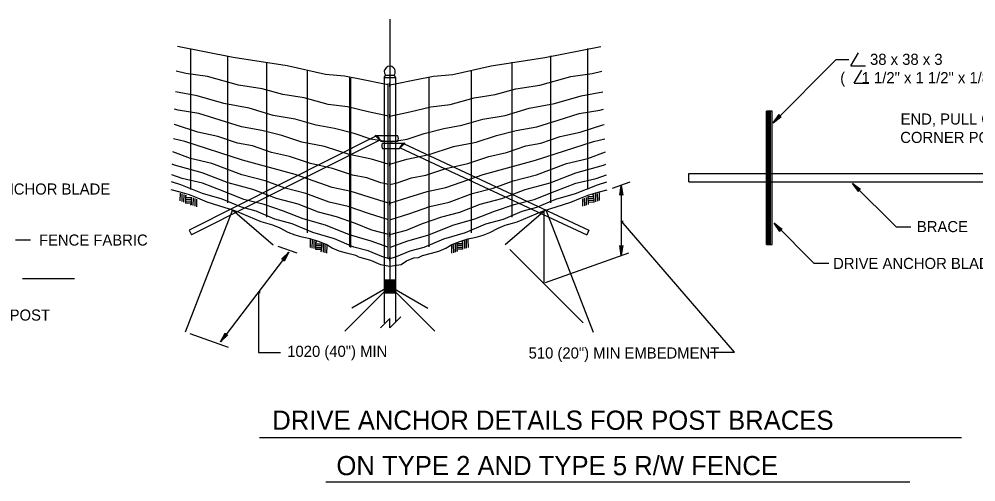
# Model space of a CAD drawing. Extents: x 13 to 918, y -903 to 879.
# Drawn here: x 370 to 639.6, y -696.9 to -566.6 of the extents above; entities that cross this region are included whole.
import ezdxf

# ---------------------------------------------------------------- set-up
doc = ezdxf.new("R2010")
doc.units = 0
for name, color, linetype in [('1', 7, 'Continuous'), ('2', 7, 'Continuous'), ('3', 7, 'Continuous')]:
    doc.layers.add(name, color=color, linetype=linetype)

msp = doc.modelspace()

# ---------------------------------------------------------------- linework, layer by layer
at = {"layer": '1'}
for p, q in [((415.3665, -615.62575), (415.33325, -617.80925)), ((415.879, -615.81125), (415.8415, -617.9945)), ((416.38525, -615.99675), (416.352, -618.178)), ((416.8935, -616.182), (416.86025, -618.36325)), ((416.86025, -617.305), (418.4915, -617.328)), ((416.8685, -616.7925), (418.49975, -616.8195)), ((416.877, -616.282), (417.181, -616.28625)), ((418.502, -616.7675), (418.4685, -618.94875)), ((419.01025, -616.953), (418.977, -619.13425)), ((419.5185, -617.13625), (419.48525, -619.3195)), ((420.029, -617.32175), (419.99575, -619.4655)), ((528.7645, -617.1905), (528.79775, -619.33425)), ((529.27475, -617.005), (529.30825, -619.18825)), ((529.78325, -616.82175), (529.8165, -619.003)), ((530.2915, -616.63625), (530.32475, -618.8175)), ((531.92475, -616.66125), (530.2935, -616.68825)), ((531.93325, -617.17375), (530.302, -617.19675)), ((531.9165, -616.15075), (531.61225, -616.155)), ((531.89975, -616.05075), (531.93325, -618.232)), ((532.40825, -615.8655), (532.4415, -618.04675)), ((532.9145, -615.68), (532.952, -617.86325)), ((533.427, -615.4945), (533.46025, -617.678)), ((416.84575, -618.328), (418.477, -618.355)), ((416.852, -617.8155), (418.48525, -617.8425)), ((418.231, -618.86325), (418.4685, -618.8655)), ((531.9415, -617.68425), (530.30825, -617.71125)), ((531.94775, -618.19675), (530.3165, -618.22375)), ((530.56225, -618.732), (530.32475, -618.73425)), ((452.0435, -628.703), (452.01025, -630.88625)), ((452.556, -628.88825), (452.5185, -631.07175)), ((453.06225, -629.07375), (453.029, -631.255)), ((453.57075, -629.25925), (453.53725, -631.4405)), ((453.53725, -630.382), (455.1685, -630.405)), ((453.54575, -629.8695), (455.177, -629.89675)), ((453.554, -629.35925), (453.85825, -629.36325)), ((455.179, -629.8445), (455.14575, -632.02575)), ((455.68725, -630.03), (455.654, -632.21125)), ((456.19575, -630.21325), (456.16225, -632.39675)), ((456.706, -630.39875), (456.67275, -632.5425)), ((491.827, -630.39875), (491.86025, -632.5425)), ((492.33725, -630.21325), (492.37075, -632.39675)), ((492.84575, -630.03), (492.879, -632.21125)), ((493.354, -629.8445), (493.38725, -632.02575)), ((494.98725, -629.8695), (493.356, -629.89675)), ((494.99575, -630.382), (493.3645, -630.405)), ((494.979, -629.35925), (494.67475, -629.36325)), ((494.96225, -629.25925), (494.99575, -631.4405)), ((495.47075, -629.07375), (495.504, -631.255)), ((495.977, -628.88825), (496.0145, -631.07175)), ((496.4895, -628.703), (496.52275, -630.88625)), ((453.52275, -631.405), (455.154, -631.432)), ((453.529, -630.8925), (455.16225, -630.9195)), ((454.90825, -631.9405), (455.14575, -631.9425)), ((495.004, -630.8925), (493.37075, -630.9195)), ((495.01025, -631.405), (493.379, -631.432)), ((493.62475, -631.9405), (493.38725, -631.9425)), ((385.57275, -639.7385), (371.00625, -639.7385))]:
    msp.add_line(p, q, dxfattribs=at)
at = {"layer": '2'}
for p, q in [((474.481, -566.63425), (474.481, -641.83625)), ((418.32275, -574.9195), (418.32275, -614.605)), ((530.21025, -574.9195), (530.21025, -614.605)), ((428.7395, -576.953), (428.7395, -618.3655)), ((439.677, -578.77375), (439.677, -622.432)), ((508.856, -578.77375), (508.856, -622.432)), ((519.7935, -576.953), (519.7935, -618.3655)), ((451.13525, -581.13425), (451.13525, -626.8445)), ((497.39775, -581.13425), (497.39775, -626.8445)), ((463.1145, -582.957), (463.1145, -630.69875)), ((463.36025, -583.2175), (463.36025, -630.95925)), ((472.9185, -583.028), (473.24775, -582.37175)), ((472.9185, -583.028), (472.9185, -652.18)), ((472.9185, -583.028), (476.0435, -583.028)), ((473.281, -582.378), (475.69775, -582.378)), ((473.877, -584.755), (473.877, -634.055)), ((475.7145, -582.37175), (476.0435, -583.028)), ((476.0435, -583.028), (476.0435, -651.94875)), ((485.4185, -582.957), (485.4185, -630.69875)), ((474.481, -585.11125), (474.481, -585.11125)), ((474.481, -585.11125), (474.481, -585.11125)), ((474.481, -585.11125), (474.481, -585.11125)), ((474.481, -585.11125), (474.481, -585.11125)), ((474.481, -585.11125), (474.481, -585.11125)), ((474.481, -585.11125), (474.481, -585.11125)), ((474.481, -585.11125), (474.481, -585.11125)), ((474.481, -593.9655), (474.481, -593.9655)), ((474.481, -593.9655), (474.481, -593.9655)), ((474.481, -593.9655), (474.481, -593.9655)), ((474.481, -593.9655), (474.481, -593.9655)), ((474.481, -593.9655), (474.481, -593.9655)), ((474.481, -593.9655), (474.481, -593.9655)), ((470.5415, -599.628), (417.97075, -626.02375)), ((471.68725, -600.70075), (418.58525, -627.36125)), ((470.379, -599.43425), (476.64775, -599.43425)), ((470.379, -599.43425), (471.9415, -600.99675)), ((471.13525, -600.1905), (471.13525, -600.1905)), ((471.9415, -600.99675), (476.64775, -600.99675)), ((472.39775, -601.5175), (478.7185, -601.5175)), ((472.39775, -603.08), (477.156, -603.08)), ((474.481, -601.257), (474.481, -601.257)), ((477.156, -603.08), (478.7185, -601.5175)), ((477.38325, -602.853), (529.94775, -627.36125)), ((478.4915, -601.7445), (530.56225, -626.02375)), ((474.481, -607.507), (474.481, -607.507)), ((474.481, -607.507), (474.481, -607.507)), ((474.481, -607.507), (474.481, -607.507)), ((474.481, -607.507), (474.481, -607.507)), ((474.481, -607.507), (474.481, -607.507)), ((474.481, -613.23625), (474.481, -613.23625)), ((423.0435, -618.153), (423.0435, -618.153)), ((474.481, -618.4445), (474.481, -618.4445)), ((474.481, -618.4445), (474.481, -618.4445)), ((474.481, -618.4445), (474.481, -618.4445)), ((474.481, -618.4445), (474.481, -618.4445)), ((525.4895, -618.153), (525.4895, -618.153)), ((430.64575, -620.92375), (430.64575, -620.92375)), ((430.64575, -620.92375), (430.64575, -620.92375)), ((517.88725, -620.92375), (517.88725, -620.92375)), ((438.22475, -623.68625), (438.22475, -623.68625)), ((474.481, -623.132), (474.481, -623.132)), ((510.30825, -623.68625), (510.30825, -623.68625)), ((417.97075, -626.02375), (418.58525, -627.36125)), ((474.481, -627.29875), (474.481, -627.29875)), ((474.481, -627.29875), (474.481, -627.29875)), ((474.481, -627.29875), (474.481, -627.29875)), ((530.56225, -626.02375), (529.94775, -627.36125)), ((474.481, -630.9445), (474.481, -630.9445)), ((474.481, -634.0695), (474.481, -634.0695)), ((474.481, -634.0695), (474.481, -634.0695)), ((474.481, -636.153), (474.481, -636.153)), ((474.481, -636.153), (474.481, -636.153)), ((472.9185, -640.0655), (476.0435, -640.0655)), ((472.9185, -640.13), (476.0435, -640.13)), ((472.9185, -640.1945), (476.0435, -640.1945)), ((472.9185, -640.26125), (476.0435, -640.26125)), ((472.9185, -640.32575), (476.0435, -640.32575)), ((472.9185, -640.3905), (476.0435, -640.3905)), ((472.9185, -640.455), (476.0435, -640.455)), ((472.9185, -640.5195), (476.0435, -640.5195)), ((472.9185, -640.58625), (476.0435, -640.58625)), ((472.9185, -640.65075), (476.0435, -640.65075)), ((472.9185, -640.7155), (476.0435, -640.7155)), ((472.9185, -640.78), (476.0435, -640.78)), ((472.9185, -640.8445), (476.0435, -640.8445)), ((472.9185, -640.91125), (476.0435, -640.91125)), ((472.9185, -640.97575), (476.0435, -640.97575)), ((472.9185, -641.0405), (476.0435, -641.0405)), ((472.9185, -641.105), (476.0435, -641.105)), ((472.9185, -641.1695), (476.0435, -641.1695)), ((472.9185, -641.23625), (476.0435, -641.23625)), ((472.9185, -641.30075), (476.0435, -641.30075)), ((472.9185, -641.3655), (476.0435, -641.3655)), ((472.9185, -641.43), (476.0435, -641.43)), ((472.9185, -641.4945), (476.0435, -641.4945)), ((472.9185, -641.56125), (476.0435, -641.56125)), ((472.9185, -641.62575), (476.0435, -641.62575)), ((472.9185, -641.6905), (476.0435, -641.6905)), ((472.9185, -641.755), (476.0435, -641.755)), ((472.9185, -641.8195), (476.0435, -641.8195)), ((472.9185, -641.88625), (476.0435, -641.88625)), ((472.9185, -641.95075), (476.0435, -641.95075)), ((472.9185, -642.0155), (476.0435, -642.0155)), ((472.9185, -642.08), (476.0435, -642.08)), ((472.9185, -642.1445), (476.0435, -642.1445)), ((472.9185, -642.21125), (476.0435, -642.21125)), ((472.9185, -642.27575), (476.0435, -642.27575)), ((472.9185, -642.3405), (476.0435, -642.3405)), ((472.9185, -642.405), (476.0435, -642.405)), ((472.9185, -642.4695), (476.0435, -642.4695)), ((472.9185, -642.53625), (476.0435, -642.53625)), ((472.9185, -642.60075), (476.0435, -642.60075)), ((472.9185, -642.6655), (476.0435, -642.6655)), ((472.9185, -642.73), (476.0435, -642.73)), ((472.9185, -642.7945), (476.0435, -642.7945)), ((472.9185, -642.86125), (476.0435, -642.86125)), ((472.9185, -642.92575), (476.0435, -642.92575)), ((472.9185, -642.9905), (476.0435, -642.9905)), ((472.9185, -643.055), (476.0435, -643.055)), ((472.9185, -643.1195), (476.0435, -643.1195)), ((472.9185, -643.18625), (476.0435, -643.18625)), ((472.9185, -643.25075), (476.0435, -643.25075)), ((472.9185, -643.3155), (476.0435, -643.3155)), ((472.9185, -643.38), (476.0435, -643.38)), ((472.9185, -643.4445), (476.0435, -643.4445)), ((472.9185, -643.51125), (476.0435, -643.51125)), ((472.9185, -643.57575), (476.0435, -643.57575)), ((472.9185, -643.6405), (476.0435, -643.6405)), ((472.9185, -643.705), (476.0435, -643.705)), ((437.452, -660.51125), (443.6935, -660.51125))]:
    msp.add_line(p, q, dxfattribs=at)
for points in [[(474.052, -585.11125), (472.51225, -584.83625), (466.99975, -583.75925), (461.71225, -582.71325), (456.32275, -582.2155), (445.51225, -579.81125), (430.36025, -577.4675), (414.59975, -574.29675)], [(474.481, -585.11125), (476.02075, -584.83625), (481.53325, -583.75925), (486.82075, -582.71325), (492.21025, -582.2155), (503.02075, -579.81125), (518.17275, -577.4675), (533.93325, -574.29675)], [(474.052, -593.9655), (474.052, -593.9655), (468.38325, -592.755), (462.529, -591.33), (457.0685, -590.63425), (450.3185, -588.80075), (444.34975, -587.82175), (438.52075, -586.282), (431.79975, -585.2405), (423.09775, -582.8155), (416.99975, -581.98425), (414.29975, -581.2675)], [(474.481, -593.9655), (474.481, -593.9655), (480.14975, -592.755), (486.004, -591.33), (491.4645, -590.63425), (498.2145, -588.80075), (504.18325, -587.82175), (510.01225, -586.282), (516.73325, -585.2405), (525.43525, -582.8155), (531.53325, -581.98425), (534.23325, -581.2675)], [(474.481, -585.65925), (474.4645, -585.4675), (474.49575, -585.357), (474.4685, -585.20925), (474.502, -585.0675), (474.4645, -584.90925), (474.4915, -584.75075), (474.481, -584.56325)], [(474.052, -601.257), (473.8645, -601.203), (469.13325, -600.38625), (464.427, -598.87175), (458.84975, -597.4445), (453.727, -596.5195), (447.82275, -594.8155), (441.577, -593.72175), (434.79775, -591.71325), (427.656, -590.405), (420.152, -588.22175), (414.04975, -587.07175)], [(474.481, -601.257), (474.6685, -601.203), (479.39975, -600.38625), (484.106, -598.87175), (489.68325, -597.4445), (494.806, -596.5195), (500.71025, -594.8155), (506.956, -593.72175), (513.73525, -591.71325), (520.877, -590.405), (528.381, -588.22175), (534.48325, -587.07175)], [(474.052, -607.507), (474.0145, -607.48625), (469.27475, -606.06125), (463.004, -604.71325), (456.08325, -602.52375), (449.69975, -601.22575), (444.02075, -599.4405), (438.43725, -597.978), (432.656, -596.957), (426.62275, -595.078), (420.66225, -593.23825), (414.86225, -592.2925), (413.83725, -592.00925)], [(474.481, -607.507), (474.5185, -607.48625), (479.25825, -606.06125), (485.529, -604.71325), (492.44975, -602.52375), (498.83325, -601.22575), (504.51225, -599.4405), (510.09575, -597.978), (515.877, -596.957), (521.91025, -595.078), (527.87075, -593.23825), (533.67075, -592.2925), (534.69575, -592.00925)], [(474.481, -594.51325), (474.4645, -594.32175), (474.49575, -594.21125), (474.4685, -594.06325), (474.502, -593.92175), (474.4645, -593.76325), (474.4915, -593.605), (474.481, -593.4175)], [(473.981, -613.228), (474.052, -613.23625), (471.96025, -612.74875), (467.98725, -611.35925), (463.9435, -610.58625), (458.2895, -608.64875), (452.1185, -607.282), (446.18725, -605.2675), (441.14575, -604.21325), (435.74975, -602.34875), (431.556, -601.53425), (426.03325, -599.63425), (420.39975, -598.4155), (414.0665, -596.34675), (413.656, -596.25075)], [(474.552, -613.228), (474.481, -613.23625), (476.57275, -612.74875), (480.54575, -611.35925), (484.5895, -610.58625), (490.2435, -608.64875), (496.4145, -607.282), (502.34575, -605.2675), (507.38725, -604.21325), (512.78325, -602.34875), (516.977, -601.53425), (522.49975, -599.63425), (528.13325, -598.4155), (534.4665, -596.34675), (534.877, -596.25075)], [(473.9915, -618.3945), (474.052, -618.4445), (468.69575, -616.755), (463.55825, -615.1195), (458.26225, -614.0175), (447.7895, -610.40925), (432.99975, -606.37175), (416.70825, -601.12375), (413.481, -600.31325)], [(474.5415, -618.3945), (474.481, -618.4445), (479.83725, -616.755), (484.97475, -615.1195), (490.27075, -614.0175), (500.7435, -610.40925), (515.53325, -606.37175), (531.82475, -601.12375), (535.052, -600.31325)], [(473.95825, -623.12375), (474.052, -623.132), (468.454, -621.37575), (462.75825, -619.41125), (457.38525, -618.20925), (450.83725, -615.753), (444.98525, -614.22175), (439.32475, -612.1445), (432.731, -610.482), (424.2935, -607.253), (418.29975, -605.857), (413.32075, -604.02375)], [(474.57475, -623.12375), (474.481, -623.132), (480.079, -621.37575), (485.77475, -619.41125), (491.14775, -618.20925), (497.69575, -615.753), (503.54775, -614.22175), (509.20825, -612.1445), (515.802, -610.482), (524.2395, -607.253), (530.23325, -605.857), (535.21225, -604.02375)], [(473.83525, -627.23825), (474.052, -627.29875), (469.404, -626.0945), (464.8395, -624.1925), (459.39975, -622.307), (454.37275, -620.96125), (448.629, -618.77375), (442.49575, -617.1655), (435.90825, -614.60075), (428.89975, -612.705), (421.602, -609.907), (413.80825, -607.753), (413.17075, -607.51325)], [(474.481, -608.055), (474.4645, -607.86325), (474.49575, -607.753), (474.4685, -607.605), (474.502, -607.46325), (474.4645, -607.305), (474.4915, -607.14675), (474.481, -606.95925)], [(474.69775, -627.23825), (474.481, -627.29875), (479.129, -626.0945), (483.6935, -624.1925), (489.13325, -622.307), (494.16025, -620.96125), (499.904, -618.77375), (506.03725, -617.1655), (512.62475, -614.60075), (519.63325, -612.705), (526.931, -609.907), (534.72475, -607.753), (535.36225, -607.51325)], [(474.052, -630.9445), (473.87075, -630.87175), (469.24575, -629.11125), (463.08725, -627.3175), (456.3415, -624.63625), (450.0665, -622.88625), (444.531, -620.69875), (439.0665, -618.83825), (433.37275, -617.407), (427.4895, -615.10075), (421.677, -612.83825), (415.95825, -611.48), (413.04575, -610.4445)], [(474.481, -630.9445), (474.66225, -630.87175), (479.28725, -629.11125), (485.44575, -627.3175), (492.1915, -624.63625), (498.4665, -622.88625), (504.002, -620.69875), (509.4665, -618.83825), (515.16025, -617.407), (521.0435, -615.10075), (526.856, -612.83825), (532.57475, -611.48), (535.48725, -610.4445)], [(474.052, -634.0695), (474.2665, -634.13425), (472.21225, -633.50925), (468.3415, -631.855), (464.35825, -630.81125), (458.84775, -628.49875), (452.78325, -626.7195), (446.99975, -624.31325), (442.0395, -622.92375), (436.78325, -620.70075), (432.654, -619.605), (427.2685, -617.33825), (421.729, -615.7445), (415.54975, -613.255), (412.95825, -612.46325)], [(474.481, -634.0695), (474.2665, -634.13425), (476.32075, -633.50925), (480.1915, -631.855), (484.17475, -630.81125), (489.68525, -628.49875), (495.74975, -626.7195), (501.53325, -624.31325), (506.4935, -622.92375), (511.74975, -620.70075), (515.879, -619.605), (521.2645, -617.33825), (526.804, -615.7445), (532.98325, -613.255), (535.57475, -612.46325)], [(465.64775, -633.557), (464.8645, -633.17375), (462.2935, -632.5405), (460.2415, -632.003), (458.2665, -631.1405), (456.56025, -630.12375), (454.33325, -629.2425), (452.052, -628.51325), (449.731, -628.03425), (447.7935, -627.478), (445.856, -626.74875), (443.53525, -625.482), (441.5395, -624.657), (439.506, -624.082), (438.22475, -623.68625), (431.0665, -620.72575), (423.0435, -618.153), (420.32475, -617.08), (417.98525, -616.103), (415.377, -615.37375), (412.86225, -614.7175)], [(482.50825, -633.7405), (483.6685, -633.17375), (486.2395, -632.5405), (488.2915, -632.003), (490.2665, -631.1405), (491.97275, -630.12375), (494.19975, -629.2425), (496.481, -628.51325), (498.802, -628.03425), (500.7395, -627.478), (502.677, -626.74875), (504.99775, -625.482), (506.9935, -624.657), (509.027, -624.082), (510.30825, -623.68625), (517.4665, -620.72575), (525.4895, -618.153), (528.20825, -617.08), (530.54775, -616.103), (533.156, -615.37375), (535.67075, -614.7175)], [(474.481, -618.9925), (474.4645, -618.80075), (474.49575, -618.6905), (474.4685, -618.5425), (474.502, -618.40075), (474.4645, -618.2425), (474.4915, -618.08425), (474.481, -617.89675)], [(474.481, -627.84675), (474.4645, -627.655), (474.49575, -627.5445), (474.4685, -627.39675), (474.502, -627.255), (474.4645, -627.09675), (474.4915, -626.93825), (474.481, -626.75075)], [(474.481, -634.6175), (474.4645, -634.42575), (474.49575, -634.3155), (474.4685, -634.1675), (474.502, -634.02575), (474.4645, -633.8675), (474.4915, -633.70925), (474.481, -633.52175)]]:
    msp.add_lwpolyline(points, dxfattribs=at)
for centre, radius, start, end in [((474.46239, -581.45496), 1.5625, 322.9296611, 217.6337972), ((469.64543, -601.73026), 2.41048, 17.7190667, 72.2809306), ((475.43208, -600.21537), 1.44511, 327.27445, 32.7255472), ((473.6597, -602.29871), 1.48416, 148.2379917, 211.7620056), ((479.45939, -603.82071), 2.41944, 107.8283861, 162.1716167)]:
    msp.add_arc(centre, radius, start, end, dxfattribs=at)
at = {"layer": '3'}
for p, q in [((604.35975, -579.795), (606.5035, -576.12425)), ((582.5035, -595.788), (600.2905, -578.001)), ((600.2905, -578.001), (603.81225, -578.001)), ((604.35975, -579.795), (608.5265, -579.795)), ((605.32875, -584.6405), (607.4725, -580.96975)), ((605.32875, -584.6405), (609.4955, -584.6405)), ((580.6015, -630.04425), (580.6015, -592.54425)), ((582.164, -592.54425), (580.6015, -592.54425)), ((580.991, -630.04425), (580.991, -592.54425)), ((581.38075, -630.04425), (581.38075, -592.54425)), ((581.77225, -630.04425), (581.77225, -592.54425)), ((582.164, -630.04425), (582.164, -592.54425)), ((558.7265, -610.12125), (652.69525, -610.12125)), ((558.7265, -612.467), (558.7265, -610.12125)), ((580.6015, -611.29425), (580.6015, -611.29425)), ((537.1895, -614.18), (542.19975, -612.40925)), ((539.69575, -613.44675), (539.69575, -633.1945)), ((558.7265, -612.467), (652.69525, -612.467)), ((558.7265, -612.467), (580.6015, -612.467)), ((604.84725, -612.865), (617.2035, -625.22125)), ((430.1395, -620.28825), (416.802, -654.78425)), ((430.1395, -620.28825), (441.58525, -630.13825)), ((518.3935, -620.28825), (506.94775, -630.13825)), ((517.88725, -620.92375), (517.88725, -641.10925)), ((518.3935, -620.28825), (531.731, -654.78425)), ((571.59975, -660.432), (539.64975, -623.42575)), ((582.73475, -624.11075), (594.04725, -635.42325)), ((617.1535, -625.11075), (621.32025, -625.11075)), ((369.027, -628.79275), (373.19375, -628.79275)), ((448.3915, -632.5445), (443.029, -630.65075)), ((580.6015, -630.04425), (582.164, -630.04425)), ((446.002, -632.25075), (426.756, -657.51125)), ((508.30825, -631.47575), (528.97475, -652.1425)), ((518.35825, -640.77175), (541.8185, -632.47175)), ((593.99725, -635.313), (598.164, -635.313)), ((437.452, -643.47375), (437.452, -660.51125)), ((461.78525, -654.532), (474.481, -641.83625)), ((474.481, -641.83625), (463.73325, -648.0425)), ((474.481, -641.83625), (487.131, -654.48425)), ((474.481, -641.83625), (485.19575, -648.02175)), ((471.84575, -653.55075), (474.481, -650.9155)), ((474.481, -653.55925), (477.5915, -650.44875)), ((474.481, -653.55925), (474.481, -650.9155)), ((429.031, -659.11125), (418.181, -655.27375)), ((564.66025, -660.432), (571.59975, -660.432)), ((437.715, -684.416), (635.60025, -684.416)), ((456.465, -696.916), (621.017, -696.916))]:
    msp.add_line(p, q, dxfattribs=at)
for points in [[(584.612, -594.1505), (584.40575, -594.08375), (582.5035, -595.788), (584.612, -594.1505), (584.789, -594.13575), (582.5035, -595.788), (584.216, -593.89625), (584.14725, -593.69625), (582.5035, -595.788), (584.15975, -593.50675), (584.14725, -593.69625)], [(539.36225, -616.0945), (539.554, -615.99675), (539.69575, -613.44675), (539.36225, -616.0945), (539.24775, -616.232), (539.69575, -613.44675), (539.82075, -615.9945), (540.01225, -616.08825), (539.69575, -613.44675), (540.13725, -616.232), (540.01225, -616.08825)], [(606.48475, -614.97325), (606.5515, -614.767), (604.84725, -612.865), (606.48475, -614.97325), (606.4995, -615.1505), (604.84725, -612.865), (606.739, -614.5775), (606.939, -614.50875), (604.84725, -612.865), (607.1285, -614.52125), (606.939, -614.50875)], [(584.37225, -626.21925), (584.439, -626.013), (582.73475, -624.11075), (584.37225, -626.21925), (584.387, -626.39625), (582.73475, -624.11075), (584.6265, -625.82325), (584.8265, -625.7545), (582.73475, -624.11075), (585.016, -625.767), (584.8265, -625.7545)], [(540.029, -630.54675), (539.83725, -630.6445), (539.69575, -633.1945), (540.029, -630.54675), (540.1435, -630.40925), (539.69575, -633.1945), (539.57075, -630.64675), (539.379, -630.553), (539.69575, -633.1945), (539.254, -630.40925), (539.379, -630.553)], [(444.13325, -634.157), (444.3435, -634.1945), (446.002, -632.25075), (444.13325, -634.157), (443.95825, -634.1945), (446.002, -632.25075), (444.55825, -634.355), (444.652, -634.5425), (446.002, -632.25075), (444.6665, -634.73425), (444.652, -634.5425)], [(465.64775, -633.557), (468.9935, -634.48825), (471.79775, -635.7155), (474.481, -636.153), (477.67475, -635.7155), (479.16025, -634.6655), (481.26025, -633.87575), (482.50825, -633.7405)], [(428.62475, -655.605), (428.4145, -655.5675), (426.756, -657.51125), (428.62475, -655.605), (428.79975, -655.5675), (426.756, -657.51125), (428.19975, -655.407), (428.106, -655.2195), (426.756, -657.51125), (428.0915, -655.028), (428.106, -655.2195)]]:
    msp.add_lwpolyline(points, dxfattribs=at)

# ---------------------------------------------------------------- texts
for s, height, p in [('38 x 38 x 3 ', 3.1249995, (609.78475, -579.5075)), ('(    1 1/2" x 1 1/2" x 1/8")', 3.1249995, (601.386, -584.676)), ('END, PULL OR', 3.1249995, (618.3995, -596.31925)), ('CORNER POST', 3.1249995, (618.3015, -601.492)), ('DRIVE ANCHOR BLADE', 3.1249995, (348.76875, -616.03025)), ('.', 3.125, (539.456, -623.8155)), ('BRACE', 3.124999, (622.987, -626.6045)), ('FENCE FABRIC', 3.1249995, (375.602, -630.399)), ("DRIVE ANCHOR BLADE (2 REQ'D)", 3.1249995, (599.3745, -636.9775)), ('.', 3.125, (437.21225, -643.79875)), ('POST', 3.124999, (367.34375, -651.5135)), ('1020 (40") MIN', 3.1249995, (445.5645, -661.72375)), ('510 (20") MIN EMBEDMENT', 3.1249995, (513.57275, -662.1925)), ('DRIVE ANCHOR DETAILS FOR POST BRACES', 5.4020865, (441.35025, -682.26175)), ('ON TYPE 2 AND TYPE 5 R/W FENCE', 5.4020865, (459.4295, -695.03275))]:
    msp.add_text(s, height=height, dxfattribs=at).set_placement(p)

doc.saveas('drawing.dxf')
